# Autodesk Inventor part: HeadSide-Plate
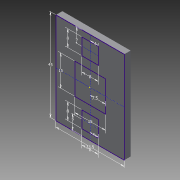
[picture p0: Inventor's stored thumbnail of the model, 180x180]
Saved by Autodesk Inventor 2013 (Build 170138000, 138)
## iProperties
Created: 2013-04
Part Number: HeadSide-Plate
Material: Generic
Document SubType Name: Modeling
Designer: frankenteddy
Density: 1 g/cm^3
Author: frankenteddy
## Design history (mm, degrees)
sketch "Sketch1"
  geometry: L1 (-16.75, 22.5)-(16.75, 22.5); L2 (16.75, 22.5)-(16.75, -22.5); L3 (16.75, -22.5)-(-16.75, -22.5); L4 (-16.75, -22.5)-(-16.75, 22.5); L5 (-4, 19.5)-(4, 19.5); L6 (4, 19.5)-(4, 11.5); L7 (4, 11.5)-(-4, 11.5); L8 (-4, 11.5)-(-4, 19.5); L9 (-4, -11.5)-(4, -11.5); L10 (4, -11.5)-(4, -19.5); L11 (4, -19.5)-(-4, -19.5); L12 (-4, -19.5)-(-4, -11.5); L13 (0, 22.5)-(0, -22.5); L14 (-7.5, 7.5)-(7.5, 7.5); L15 (7.5, 7.5)-(7.5, -7.5); L16 (7.5, -7.5)-(-7.5, -7.5); L17 (-7.5, -7.5)-(-7.5, 7.5); L18 (-4, 15.5)-(4, 15.5); L19 (-7.5, 0)-(7.5, 0); L20 (-4, -15.5)-(4, -15.5); L21 (-16.75, 0)-(16.75, 0); 1 further point
  constraints: 42 end point, 10 midpoint, 9 parallel, 4 horizontal, 4 perpendicular, 1 collinear, 1 horizontal alignment, 1 vertical alignment
  dimensions: "d0" = 33.5 distance of L2.end L3.end; "d1" = 45 distance of L1.end L2.end; "d2" = 8 distance of L6.end L7.end; "d3" = 8 distance of L5.end L6.end; "d4" = 8 distance of L10.end L11.end; "d5" = 8 distance of L9.end L10.end; "d6" = 15 distance of L15.end L16.end; "d7" = 15 distance of L14.end L15.end; "d8" = 4 distance between parallel lines of L13 L8; "d9" = 7.5 distance between parallel lines of L13 L17; "d10" = 4 distance between parallel lines of L13 L12; "d11" = 7 distance between parallel lines of L20 L3; "d12" = 7 distance between parallel lines of L18 L1
extrude "Extrusion1" new body sketch "Sketch1" distance "d13" = 1.62; taper "d14" = 0 deg
extrude "Extrusion2" join sketch "Sketch1" distance "d15" = 5.12; taper "d16" = 0 deg
extrude "Extrusion3" join sketch "Sketch1" distance "d17" = 6.12; taper "d18" = 0 deg
sketch "Sketch3"
  geometry: L1 (-7.5, -7.5)-(7.5, -7.5) reference; L2 (7.5, -7.5)-(7.5, 7.5) reference; L3 (7.5, 7.5)-(-7.5, 7.5) reference; L4 (-7.5, 7.5)-(-7.5, -7.5) reference; L5 (0, 7.5)-(0, -7.5); 2 further points
  constraints: 2 end point, 2 midpoint, 1 coincident
workplane "Work Plane1"
sketch "Sketch4"
  geometry: L1 (-0.056, 7.5)-(-3.056, 7.5); L2 (-3.056, 7.5)-(-3.056, 15); L3 (-3.056, 15)-(-0.056, 15); L4 (-0.056, 15)-(-0.056, 7.5); L5 (4.944, 7.5)-(-3.056, 7.5); L6 (-3.056, 7.5)-(-3.056, 3.5); A1 r 5 centre (-0.056, 7.5) between (-3.056, 3.5) and (-3.056, 11.5); 2 further points
  constraints: 12 end point, 3 perpendicular, 3 point on circle, 2 parallel, 1 centre point, 1 coincident, 1 horizontal, 1 midpoint, 1 point on line, 1 other
  dimensions: "d22" = 3 distance of L2.end L3.end; "d23" = 7.5 distance of L1.end L2.end; "d24" = 10 diameter of A1
revolve "Revolution1" sketch "Sketch4" stored, may be unused: angle "d25" = 90 deg
sketch "Sketch5"
  geometry: L1 (-4, -19.5)-(4, -19.5) reference; L2 (4, -19.5)-(4, -11.5) reference; L3 (4, -11.5)-(-4, -11.5) reference; L4 (-4, -11.5)-(-4, -19.5) reference; L5 (-4, -11.5)-(4, -11.5); L6 (4, -11.5)-(4, -19.5); L7 (4, -19.5)-(-4, -19.5); L8 (-4, -19.5)-(-4, -11.5); L9 (0, -11.5)-(0, -19.5); L10 (-4, -15.5)-(4, -15.5); L11 (-2, -13.5)-(2, -13.5); L12 (2, -13.5)-(2, -17.5); L13 (2, -17.5)-(-2, -17.5); L14 (-2, -17.5)-(-2, -13.5); 1 further point
  constraints: 20 end point, 4 midpoint, 4 parallel, 2 horizontal, 2 perpendicular
  dimensions: "d26" = 2 distance between parallel lines of L11 L3; "d27" = 2 distance between parallel lines of L1 L13; "d28" = 2 distance between parallel lines of L2 L12; "d29" = 2 distance between parallel lines of L4 L14
extrude "Extrusion5" join sketch "Sketch5" distance "d30" = 2; taper "d31" = 0 deg
mirror "Mirror1"
extrude "Extrusion7" join sketch "Sketch1" distance "d34" = 3.12; taper "d35" = 0 deg
body "Solid1"
